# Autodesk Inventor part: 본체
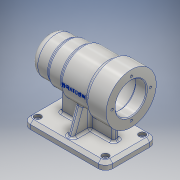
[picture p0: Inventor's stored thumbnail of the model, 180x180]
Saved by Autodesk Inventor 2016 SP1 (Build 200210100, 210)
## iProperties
Created: 2016-06
Part Number: 본체
Material: 알루미늄 6061
Document SubType Name: Modeling
Designer: basic
Density: 2.7 g/cm^3
Appearance: 알루미늄 - 평지
Mass: 668.587 g
Surface Area: 646.96 cm^2
Volume: 247.625 cm^3
Author: basic
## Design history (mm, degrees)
sketch "스케치1"
  geometry: L1 (56, 0)-(-56, 0); L2 (56, 0)-(56, 15); L3 (46, 25)-(31, 25); L4 (31, 25)-(31, 27); L5 (31, 27)-(11, 27); L6 (11, 27)-(11, 30); L7 (11, 30)-(-28, 30); L8 (-28, 30)-(-28, 34); L9 (-28, 34)-(-56, 34); L10 (-56, 34)-(-56, 0); L11 (-56, 21)-(-41, 21); L12 (-41, 21)-(-41, 21); L13 (-38, 24)-(10, 24); L14 (13, 21)-(13, 21); L15 (13, 21)-(25, 21); L16 (25, 21)-(25, 17.5); L17 (25, 17.5)-(43, 17.5); L18 (43, 17.5)-(43, 16); L19 (43, 16)-(47, 16); L20 (47, 16)-(47, 10.5); L21 (47, 10.5)-(47, 10.5); L22 (50, 7.5)-(50, 0); A1 r 10 centre (46, 15) between (56, 15) and (46, 25); A2 r 3 centre (-38, 21) between (-38, 24) and (-41, 21); A3 r 3 centre (10, 21) between (13, 21) and (10, 24); A4 r 3 centre (47, 7.5) between (50, 7.5) and (47, 10.5); 6 further points
  constraints: 44 end point, 17 perpendicular, 12 point on line, 8 point on circle, 8 tangent, 4 centre point, 2 equal radius, 2 horizontal, 2 vertical, 1 coincident, 1 midpoint
  dimensions: "d0" = 112 distance of L1.start L1.end; "d1" = 25 distance of point (56, 25) L3.end; "d3" = 45 distance between parallel lines of L6 L2; "d4" = 84 distance between parallel lines of L8 L2; "d5" = 50 diameter of L3 L1; "d6" = 68 diameter of L9 L1; "d7" = 60 diameter of L7 L1; "d8" = 54 diameter of L5 L1; "d9" = 10 radius of A1; "d10" = 42 diameter of L11 L1; "d11" = 48 diameter of L13 L1; "d12" = 35 diameter of L17 L1; "d13" = 32 diameter of L19 L1; "d14" = 21 diameter of L21 L1; "d15" = 15 distance of L11.start L11.end; "d16" = 54 distance of point (-41, 24) point (13, 24); "d17" = 12 distance of L14.end L15.end; "d18" = 18 distance of L16.end L17.end; "d19" = 3 distance of L20.end point (50, 10.5); "d20" = 4 distance of L18.end L19.end; "d21" = 3 radius of A2
revolve "회전1" sketch "스케치1" stored, may be unused: angle "d22" = 90 deg
chamfer "모따기1" distance "d23" = 1; stored, may be unused: second distance "d24" = 2, angle "d25" = 45 deg
node "작업 평면1"
sketch "스케치2"
  geometry: L1 (46, -35)-(-46, -35); L2 (-56, -25)-(-56, 25); L3 (-46, 35)-(46, 35); L4 (56, 25)-(56, -25); L5 (56, -35)-(-56, 35); L6 (-56, -35)-(56, 35); A1 r 10 centre (-46, -25) between (-56, -25) and (-46, -35); A2 r 10 centre (46, -25) between (46, -35) and (56, -25); A3 r 10 centre (46, 25) between (56, 25) and (46, 35); A4 r 10 centre (-46, 25) between (-46, 35) and (-56, 25); 1 further point
  constraints: 12 end point, 8 point on circle, 8 point on line, 8 tangent, 4 centre point, 3 equal radius, 2 midpoint, 2 parallel, 1 horizontal, 1 perpendicular
  dimensions: "d27" = 70 distance of L6.start L5.end; "d28" = 112 distance of L5.start L6.start; "d29" = 10 radius of A1
extrude "돌출1" join sketch "스케치2" distance "d30" = 10; taper "d31" = 0 deg
sketch "스케치4"
  geometry: L1 (-56, 25)-(-56, -25) reference; L2 (-36, -4)-(36, -4); L3 (36, -4)-(36, 4); L4 (36, 4)-(-36, 4); L5 (-36, 4)-(-36, -4); L6 (-36, -4)-(36, 4); L7 (36, -4)-(-36, 4); 1 further point
  constraints: 12 end point, 2 midpoint, 2 parallel, 1 horizontal, 1 perpendicular
  dimensions: "d36" = 20 distance between parallel lines of L1 L5; "d37" = 8 distance of L2.end L3.end
extrude "돌출3" join sketch "스케치4" stored distance "d38" = 8; taper "d39" = 0 deg
sketch "스케치6"
  geometry: L1 (-35, -70)-(-35, -60) reference; L2 (-35, -60)-(-4, -60) reference; L3 (-4, -60)-(-4, -29.732) reference; L4 (4, -29.732)-(4, -60) reference; L5 (4, -60)-(35, -60) reference; L6 (35, -60)-(35, -70) reference; L7 (35, -70)-(-35, -70) reference; L8 (-28, -60)-(-15.509, -25.68); C1 r 24 at (0, 0) reference; A1 r 30 centre (0, 0) between (4, -29.732) and (-4, -29.732) reference; 1 further point
  constraints: 2 end point, 1 point on circle, 1 point on line
  dimensions: "d41" = 7 distance from line of L1 L8.start; "d42" = 20 deg angle of L1 L8
feature "리브1" sketch "스케치6" dims "d43" = 1, "d44" = 8, "d45" = 0, "d46" = 0, "d47" = 1, "d48" = 1
chamfer "모따기2" distance "d49" = 4; stored, may be unused: second distance "d50" = 2, angle "d51" = 45 deg
sketch "스케치8"
  geometry: A1 r 6 centre (-46, -25) between (-52, -25) and (-46, -31) reference; 2 further points
  constraints: 1 coincident
hole "구멍1" sketch "스케치8" at (-46, -25) diameter "d52" = 5; stored, may be unused: countersink angle "d56" = 90 deg, drill point angle "d58" = 118 deg; dims "d53" = 6, "d54" = 9, "d55" = 4, "d57" = 8
fillet "모깎기1" dims "d59" = 0.3
sketch "스케치9"
  geometry: L1 (0, 0)-(-26, 0); C1 r 22 at (0, 0) reference; 1 further point
  constraints: 2 end point, 1 coincident, 1 horizontal
  dimensions: "d60" = 26 distance of L1.start L1.end
hole "구멍2" sketch "스케치9" at (-26, 0) diameter "d61" = 3.242; stored, may be unused: countersink angle "d65" = 90 deg, drill point angle "d67" = 118 deg; dims "d62" = 8, "d63" = 9, "d64" = 4, "d66" = 11
fillet "모깎기2" dims "d71" = 3
fillet "모깎기3" dims "d72" = 3
fillet "모깎기4" dims "d73" = 3
node "작업 평면3"
sketch "스케치11"
  geometry: L1 (56, 34)-(56, -34) reference; L2 (-46, -70)-(46, -70) reference; 2 further points
  constraints: 1 other
  dimensions: "d77" = 48 distance from line of L1 point (8, 0); "d78" = 0 vertical distance of point (0, 0) point (8, 0)
feature "엠보싱1" sketch "스케치11" dims "d0" = 112, "d1" = 25, "d3" = 45, "d4" = 84, "d5" = 50, "d6" = 68, "d7" = 60, "d8" = 54, "d9" = 10, "d10" = 42, "d11" = 48, "d12" = 35, "d13" = 32, "d14" = 21, "d15" = 15, "d16" = 54, "d17" = 12, "d18" = 18, "d19" = 3, "d20" = 4, "d21" = 3, "d79" = 0.5, "d80" = 0
fillet "모깎기5" dims "d81" = 3
node "솔리드1"
mirror "대칭1"
mirror "대칭2"
mirror "대칭3"
pattern_circular "원형 패턴1" dims angle "d69" = 360 deg
node "절단 모서리 투영2"
other parameters: "d76" = -30.5
